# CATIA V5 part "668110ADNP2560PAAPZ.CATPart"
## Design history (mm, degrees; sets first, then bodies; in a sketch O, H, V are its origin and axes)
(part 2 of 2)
    point P17 (-10.9793, 9.5)
    point P18 (-10.4378, 10.4378)
    line L9 (-10.9793, 9.5) -> (-10.4378, 10.4378)
    point P19 (-10.4378, 10.4378)
    point P20 (-9.5, 10.9793)
    line L10 (-10.4378, 10.4378) -> (-9.5, 10.9793)
    point P21 (-9.5, 10.9793)
    point P22 (-9.5, 12.0622)
    line L11 (-9.5, 10.9793) -> (-9.5, 12.0622)
    point P23 (-9.5, 12.0622)
    point P24 (-8.9585, 13)
    line L12 (-9.5, 12.0622) -> (-8.9585, 13)
    point P25 (-8.9585, 13)
    point P26 (-9.5, 13.9378)
    line L13 (-8.9585, 13) -> (-9.5, 13.9378)
    point P27 (-9.5, 13.9378)
    point P28 (-9.5, 15.0207)
    line L14 (-9.5, 13.9378) -> (-9.5, 15.0207)
    point P29 (-9.5, 15.0207)
    point P30 (-10.4378, 15.5622)
    line L15 (-9.5, 15.0207) -> (-10.4378, 15.5622)
    point P31 (-10.4378, 15.5622)
    point P32 (-10.9793, 16.5)
    line L16 (-10.4378, 15.5622) -> (-10.9793, 16.5)
    point P33 (-10.9793, 16.5)
    point P34 (-12.0622, 16.5)
    line L17 (-10.9793, 16.5) -> (-12.0622, 16.5)
    point P35 (-12.0622, 16.5)
    point P36 (-13, 17.0415)
    line L18 (-12.0622, 16.5) -> (-13, 17.0415)
    point P37 (-13, 17.0415)
    point P38 (-13.9378, 16.5)
    line L19 (-13, 17.0415) -> (-13.9378, 16.5)
    point P39 (-13.9378, 16.5)
    point P40 (-15.0207, 16.5)
    line L20 (-13.9378, 16.5) -> (-15.0207, 16.5)
    point P41 (-15.0207, 16.5)
    point P42 (-15.5622, 15.5622)
    line L21 (-15.0207, 16.5) -> (-15.5622, 15.5622)
    point P43 (-15.5622, 15.5622)
    point P44 (-16.5, 15.0207)
    line L22 (-15.5622, 15.5622) -> (-16.5, 15.0207)
    point P45 (-16.5, 15.0207)
    point P46 (-16.5, 13.9378)
    line L23 (-16.5, 15.0207) -> (-16.5, 13.9378)
    point P47 (-16.5, 13.9378)
    point P48 (-17.0415, 13)
    line L24 (-16.5, 13.9378) -> (-17.0415, 13)
    coincidence: P1 P48, P2 P3, P4 P5, P6 P7, P8 P9, P10 P11, P12 P13, P14 P15, P16 P17, P18 P19, P20 P21, P22 P23, P24 P25, P26 P27, P28 P29, P30 P31, P32 P33, P34 P35, P36 P37, P38 P39, P40 P41, P42 P43, P44 P45, P46 P47
  Pocket3: profile Sketch24, direction (0, 0, -1), length 4.4
  Sketch25 on Plane25, origin (0, 0, 0), H (1, 0, 0), V (0, 1, 0)
    point P1 (8.9585, -13)
    point P2 (9.5, -13.9378)
    line L1 (8.9585, -13) -> (9.5, -13.9378)
    point P3 (9.5, -13.9378)
    point P4 (9.5, -15.0207)
    line L2 (9.5, -13.9378) -> (9.5, -15.0207)
    point P5 (9.5, -15.0207)
    point P6 (10.4378, -15.5622)
    line L3 (9.5, -15.0207) -> (10.4378, -15.5622)
    point P7 (10.4378, -15.5622)
    point P8 (10.9793, -16.5)
    line L4 (10.4378, -15.5622) -> (10.9793, -16.5)
    point P9 (10.9793, -16.5)
    point P10 (12.0622, -16.5)
    line L5 (10.9793, -16.5) -> (12.0622, -16.5)
    point P11 (12.0622, -16.5)
    point P12 (13, -17.0415)
    line L6 (12.0622, -16.5) -> (13, -17.0415)
    point P13 (13, -17.0415)
    point P14 (13.9378, -16.5)
    line L7 (13, -17.0415) -> (13.9378, -16.5)
    point P15 (13.9378, -16.5)
    point P16 (15.0207, -16.5)
    line L8 (13.9378, -16.5) -> (15.0207, -16.5)
    point P17 (15.0207, -16.5)
    point P18 (15.5622, -15.5622)
    line L9 (15.0207, -16.5) -> (15.5622, -15.5622)
    point P19 (15.5622, -15.5622)
    point P20 (16.5, -15.0207)
    line L10 (15.5622, -15.5622) -> (16.5, -15.0207)
    point P21 (16.5, -15.0207)
    point P22 (16.5, -13.9378)
    line L11 (16.5, -15.0207) -> (16.5, -13.9378)
    point P23 (16.5, -13.9378)
    point P24 (17.0415, -13)
    line L12 (16.5, -13.9378) -> (17.0415, -13)
    point P25 (17.0415, -13)
    point P26 (16.5, -12.0622)
    line L13 (17.0415, -13) -> (16.5, -12.0622)
    point P27 (16.5, -12.0622)
    point P28 (16.5, -10.9793)
    line L14 (16.5, -12.0622) -> (16.5, -10.9793)
    point P29 (16.5, -10.9793)
    point P30 (15.5622, -10.4378)
    line L15 (16.5, -10.9793) -> (15.5622, -10.4378)
    point P31 (15.5622, -10.4378)
    point P32 (15.0207, -9.5)
    line L16 (15.5622, -10.4378) -> (15.0207, -9.5)
    point P33 (15.0207, -9.5)
    point P34 (13.9378, -9.5)
    line L17 (15.0207, -9.5) -> (13.9378, -9.5)
    point P35 (13.9378, -9.5)
    point P36 (13, -8.9585)
    line L18 (13.9378, -9.5) -> (13, -8.9585)
    point P37 (13, -8.9585)
    point P38 (12.0622, -9.5)
    line L19 (13, -8.9585) -> (12.0622, -9.5)
    point P39 (12.0622, -9.5)
    point P40 (10.9793, -9.5)
    line L20 (12.0622, -9.5) -> (10.9793, -9.5)
    point P41 (10.9793, -9.5)
    point P42 (10.4378, -10.4378)
    line L21 (10.9793, -9.5) -> (10.4378, -10.4378)
    point P43 (10.4378, -10.4378)
    point P44 (9.5, -10.9793)
    line L22 (10.4378, -10.4378) -> (9.5, -10.9793)
    point P45 (9.5, -10.9793)
    point P46 (9.5, -12.0622)
    line L23 (9.5, -10.9793) -> (9.5, -12.0622)
    point P47 (9.5, -12.0622)
    point P48 (8.9585, -13)
    line L24 (9.5, -12.0622) -> (8.9585, -13)
    coincidence: P1 P48, P2 P3, P4 P5, P6 P7, P8 P9, P10 P11, P12 P13, P14 P15, P16 P17, P18 P19, P20 P21, P22 P23, P24 P25, P26 P27, P28 P29, P30 P31, P32 P33, P34 P35, P36 P37, P38 P39, P40 P41, P42 P43, P44 P45, P46 P47
  Pocket4: profile Sketch25, direction (0, 0, -1), length 4.4
  Sketch26 on Plane26, origin (0, 0, 0), H (1, 0, 0), V (0, 1, 0)
    point P1 (8.9585, 13)
    point P2 (9.5, 12.0622)
    line L1 (8.9585, 13) -> (9.5, 12.0622)
    point P3 (9.5, 12.0622)
    point P4 (9.5, 10.9793)
    line L2 (9.5, 12.0622) -> (9.5, 10.9793)
    point P5 (9.5, 10.9793)
    point P6 (10.4378, 10.4378)
    line L3 (9.5, 10.9793) -> (10.4378, 10.4378)
    point P7 (10.4378, 10.4378)
    point P8 (10.9793, 9.5)
    line L4 (10.4378, 10.4378) -> (10.9793, 9.5)
    point P9 (10.9793, 9.5)
    point P10 (12.0622, 9.5)
    line L5 (10.9793, 9.5) -> (12.0622, 9.5)
    point P11 (12.0622, 9.5)
    point P12 (13, 8.9585)
    line L6 (12.0622, 9.5) -> (13, 8.9585)
    point P13 (13, 8.9585)
    point P14 (13.9378, 9.5)
    line L7 (13, 8.9585) -> (13.9378, 9.5)
    point P15 (13.9378, 9.5)
    point P16 (15.0207, 9.5)
    line L8 (13.9378, 9.5) -> (15.0207, 9.5)
    point P17 (15.0207, 9.5)
    point P18 (15.5622, 10.4378)
    line L9 (15.0207, 9.5) -> (15.5622, 10.4378)
    point P19 (15.5622, 10.4378)
    point P20 (16.5, 10.9793)
    line L10 (15.5622, 10.4378) -> (16.5, 10.9793)
    point P21 (16.5, 10.9793)
    point P22 (16.5, 12.0622)
    line L11 (16.5, 10.9793) -> (16.5, 12.0622)
    point P23 (16.5, 12.0622)
    point P24 (17.0415, 13)
    line L12 (16.5, 12.0622) -> (17.0415, 13)
    point P25 (17.0415, 13)
    point P26 (16.5, 13.9378)
    line L13 (17.0415, 13) -> (16.5, 13.9378)
    point P27 (16.5, 13.9378)
    point P28 (16.5, 15.0207)
    line L14 (16.5, 13.9378) -> (16.5, 15.0207)
    point P29 (16.5, 15.0207)
    point P30 (15.5622, 15.5622)
    line L15 (16.5, 15.0207) -> (15.5622, 15.5622)
    point P31 (15.5622, 15.5622)
    point P32 (15.0207, 16.5)
    line L16 (15.5622, 15.5622) -> (15.0207, 16.5)
    point P33 (15.0207, 16.5)
    point P34 (13.9378, 16.5)
    line L17 (15.0207, 16.5) -> (13.9378, 16.5)
    point P35 (13.9378, 16.5)
    point P36 (13, 17.0415)
    line L18 (13.9378, 16.5) -> (13, 17.0415)
    point P37 (13, 17.0415)
    point P38 (12.0622, 16.5)
    line L19 (13, 17.0415) -> (12.0622, 16.5)
    point P39 (12.0622, 16.5)
    point P40 (10.9793, 16.5)
    line L20 (12.0622, 16.5) -> (10.9793, 16.5)
    point P41 (10.9793, 16.5)
    point P42 (10.4378, 15.5622)
    line L21 (10.9793, 16.5) -> (10.4378, 15.5622)
    point P43 (10.4378, 15.5622)
    point P44 (9.5, 15.0207)
    line L22 (10.4378, 15.5622) -> (9.5, 15.0207)
    point P45 (9.5, 15.0207)
    point P46 (9.5, 13.9378)
    line L23 (9.5, 15.0207) -> (9.5, 13.9378)
    point P47 (9.5, 13.9378)
    point P48 (8.9585, 13)
    line L24 (9.5, 13.9378) -> (8.9585, 13)
    coincidence: P1 P48, P2 P3, P4 P5, P6 P7, P8 P9, P10 P11, P12 P13, P14 P15, P16 P17, P18 P19, P20 P21, P22 P23, P24 P25, P26 P27, P28 P29, P30 P31, P32 P33, P34 P35, P36 P37, P38 P39, P40 P41, P42 P43, P44 P45, P46 P47
  Pocket5: profile Sketch26, direction (0, 0, -1), length 4.4
  Sketch27 on Plane27, origin (0, 0, -99), H (1, 0, 0), V (0, 1, 0)
    point P1 (-17.0415, 13)
    point P2 (-16.5, 12.0622)
    line L1 (-17.0415, 13) -> (-16.5, 12.0622)
    point P3 (-16.5, 12.0622)
    point P4 (-16.5, 10.9793)
    line L2 (-16.5, 12.0622) -> (-16.5, 10.9793)
    point P5 (-16.5, 10.9793)
    point P6 (-15.5622, 10.4378)
    line L3 (-16.5, 10.9793) -> (-15.5622, 10.4378)
    point P7 (-15.5622, 10.4378)
    point P8 (-15.0207, 9.5)
    line L4 (-15.5622, 10.4378) -> (-15.0207, 9.5)
    point P9 (-15.0207, 9.5)
    point P10 (-13.9378, 9.5)
    line L5 (-15.0207, 9.5) -> (-13.9378, 9.5)
    point P11 (-13.9378, 9.5)
    point P12 (-13, 8.9585)
    line L6 (-13.9378, 9.5) -> (-13, 8.9585)
    point P13 (-13, 8.9585)
    point P14 (-12.0622, 9.5)
    line L7 (-13, 8.9585) -> (-12.0622, 9.5)
    point P15 (-12.0622, 9.5)
    point P16 (-10.9793, 9.5)
    line L8 (-12.0622, 9.5) -> (-10.9793, 9.5)
    point P17 (-10.9793, 9.5)
    point P18 (-10.4378, 10.4378)
    line L9 (-10.9793, 9.5) -> (-10.4378, 10.4378)
    point P19 (-10.4378, 10.4378)
    point P20 (-9.5, 10.9793)
    line L10 (-10.4378, 10.4378) -> (-9.5, 10.9793)
    point P21 (-9.5, 10.9793)
    point P22 (-9.5, 12.0622)
    line L11 (-9.5, 10.9793) -> (-9.5, 12.0622)
    point P23 (-9.5, 12.0622)
    point P24 (-8.9585, 13)
    line L12 (-9.5, 12.0622) -> (-8.9585, 13)
    point P25 (-8.9585, 13)
    point P26 (-9.5, 13.9378)
    line L13 (-8.9585, 13) -> (-9.5, 13.9378)
    point P27 (-9.5, 13.9378)
    point P28 (-9.5, 15.0207)
    line L14 (-9.5, 13.9378) -> (-9.5, 15.0207)
    point P29 (-9.5, 15.0207)
    point P30 (-10.4378, 15.5622)
    line L15 (-9.5, 15.0207) -> (-10.4378, 15.5622)
    point P31 (-10.4378, 15.5622)
    point P32 (-10.9793, 16.5)
    line L16 (-10.4378, 15.5622) -> (-10.9793, 16.5)
    point P33 (-10.9793, 16.5)
    point P34 (-12.0622, 16.5)
    line L17 (-10.9793, 16.5) -> (-12.0622, 16.5)
    point P35 (-12.0622, 16.5)
    point P36 (-13, 17.0415)
    line L18 (-12.0622, 16.5) -> (-13, 17.0415)
    point P37 (-13, 17.0415)
    point P38 (-13.9378, 16.5)
    line L19 (-13, 17.0415) -> (-13.9378, 16.5)
    point P39 (-13.9378, 16.5)
    point P40 (-15.0207, 16.5)
    line L20 (-13.9378, 16.5) -> (-15.0207, 16.5)
    point P41 (-15.0207, 16.5)
    point P42 (-15.5622, 15.5622)
    line L21 (-15.0207, 16.5) -> (-15.5622, 15.5622)
    point P43 (-15.5622, 15.5622)
    point P44 (-16.5, 15.0207)
    line L22 (-15.5622, 15.5622) -> (-16.5, 15.0207)
    point P45 (-16.5, 15.0207)
    point P46 (-16.5, 13.9378)
    line L23 (-16.5, 15.0207) -> (-16.5, 13.9378)
    point P47 (-16.5, 13.9378)
    point P48 (-17.0415, 13)
    line L24 (-16.5, 13.9378) -> (-17.0415, 13)
    coincidence: P1 P48, P2 P3, P4 P5, P6 P7, P8 P9, P10 P11, P12 P13, P14 P15, P16 P17, P18 P19, P20 P21, P22 P23, P24 P25, P26 P27, P28 P29, P30 P31, P32 P33, P34 P35, P36 P37, P38 P39, P40 P41, P42 P43, P44 P45, P46 P47
  Pocket6: profile Sketch27, direction (0, 0, 1), length 4.4
  Sketch28 on Plane28, origin (0, 0, -99), H (1, 0, 0), V (0, 1, 0)
    point P1 (-17.0415, -13)
    point P2 (-16.5, -13.9378)
    line L1 (-17.0415, -13) -> (-16.5, -13.9378)
    point P3 (-16.5, -13.9378)
    point P4 (-16.5, -15.0207)
    line L2 (-16.5, -13.9378) -> (-16.5, -15.0207)
    point P5 (-16.5, -15.0207)
    point P6 (-15.5622, -15.5622)
    line L3 (-16.5, -15.0207) -> (-15.5622, -15.5622)
    point P7 (-15.5622, -15.5622)
    point P8 (-15.0207, -16.5)
    line L4 (-15.5622, -15.5622) -> (-15.0207, -16.5)
    point P9 (-15.0207, -16.5)
    point P10 (-13.9378, -16.5)
    line L5 (-15.0207, -16.5) -> (-13.9378, -16.5)
    point P11 (-13.9378, -16.5)
    point P12 (-13, -17.0415)
    line L6 (-13.9378, -16.5) -> (-13, -17.0415)
    point P13 (-13, -17.0415)
    point P14 (-12.0622, -16.5)
    line L7 (-13, -17.0415) -> (-12.0622, -16.5)
    point P15 (-12.0622, -16.5)
    point P16 (-10.9793, -16.5)
    line L8 (-12.0622, -16.5) -> (-10.9793, -16.5)
    point P17 (-10.9793, -16.5)
    point P18 (-10.4378, -15.5622)
    line L9 (-10.9793, -16.5) -> (-10.4378, -15.5622)
    point P19 (-10.4378, -15.5622)
    point P20 (-9.5, -15.0207)
    line L10 (-10.4378, -15.5622) -> (-9.5, -15.0207)
    point P21 (-9.5, -15.0207)
    point P22 (-9.5, -13.9378)
    line L11 (-9.5, -15.0207) -> (-9.5, -13.9378)
    point P23 (-9.5, -13.9378)
    point P24 (-8.9585, -13)
    line L12 (-9.5, -13.9378) -> (-8.9585, -13)
    point P25 (-8.9585, -13)
    point P26 (-9.5, -12.0622)
    line L13 (-8.9585, -13) -> (-9.5, -12.0622)
    point P27 (-9.5, -12.0622)
    point P28 (-9.5, -10.9793)
    line L14 (-9.5, -12.0622) -> (-9.5, -10.9793)
    point P29 (-9.5, -10.9793)
    point P30 (-10.4378, -10.4378)
    line L15 (-9.5, -10.9793) -> (-10.4378, -10.4378)
    point P31 (-10.4378, -10.4378)
    point P32 (-10.9793, -9.5)
    line L16 (-10.4378, -10.4378) -> (-10.9793, -9.5)
    point P33 (-10.9793, -9.5)
    point P34 (-12.0622, -9.5)
    line L17 (-10.9793, -9.5) -> (-12.0622, -9.5)
    point P35 (-12.0622, -9.5)
    point P36 (-13, -8.9585)
    line L18 (-12.0622, -9.5) -> (-13, -8.9585)
    point P37 (-13, -8.9585)
    point P38 (-13.9378, -9.5)
    line L19 (-13, -8.9585) -> (-13.9378, -9.5)
    point P39 (-13.9378, -9.5)
    point P40 (-15.0207, -9.5)
    line L20 (-13.9378, -9.5) -> (-15.0207, -9.5)
    point P41 (-15.0207, -9.5)
    point P42 (-15.5622, -10.4378)
    line L21 (-15.0207, -9.5) -> (-15.5622, -10.4378)
    point P43 (-15.5622, -10.4378)
    point P44 (-16.5, -10.9793)
    line L22 (-15.5622, -10.4378) -> (-16.5, -10.9793)
    point P45 (-16.5, -10.9793)
    point P46 (-16.5, -12.0622)
    line L23 (-16.5, -10.9793) -> (-16.5, -12.0622)
    point P47 (-16.5, -12.0622)
    point P48 (-17.0415, -13)
    line L24 (-16.5, -12.0622) -> (-17.0415, -13)
    coincidence: P1 P48, P2 P3, P4 P5, P6 P7, P8 P9, P10 P11, P12 P13, P14 P15, P16 P17, P18 P19, P20 P21, P22 P23, P24 P25, P26 P27, P28 P29, P30 P31, P32 P33, P34 P35, P36 P37, P38 P39, P40 P41, P42 P43, P44 P45, P46 P47
  Pocket7: profile Sketch28, direction (0, 0, 1), length 4.4
  Sketch29 on Plane29, origin (0, 0, -99), H (1, 0, 0), V (0, 1, 0)
    point P1 (8.9585, -13)
    point P2 (9.5, -13.9378)
    line L1 (8.9585, -13) -> (9.5, -13.9378)
    point P3 (9.5, -13.9378)
    point P4 (9.5, -15.0207)
    line L2 (9.5, -13.9378) -> (9.5, -15.0207)
    point P5 (9.5, -15.0207)
    point P6 (10.4378, -15.5622)
    line L3 (9.5, -15.0207) -> (10.4378, -15.5622)
    point P7 (10.4378, -15.5622)
    point P8 (10.9793, -16.5)
    line L4 (10.4378, -15.5622) -> (10.9793, -16.5)
    point P9 (10.9793, -16.5)
    point P10 (12.0622, -16.5)
    line L5 (10.9793, -16.5) -> (12.0622, -16.5)
    point P11 (12.0622, -16.5)
    point P12 (13, -17.0415)
    line L6 (12.0622, -16.5) -> (13, -17.0415)
    point P13 (13, -17.0415)
    point P14 (13.9378, -16.5)
    line L7 (13, -17.0415) -> (13.9378, -16.5)
    point P15 (13.9378, -16.5)
    point P16 (15.0207, -16.5)
    line L8 (13.9378, -16.5) -> (15.0207, -16.5)
    point P17 (15.0207, -16.5)
    point P18 (15.5622, -15.5622)
    line L9 (15.0207, -16.5) -> (15.5622, -15.5622)
    point P19 (15.5622, -15.5622)
    point P20 (16.5, -15.0207)
    line L10 (15.5622, -15.5622) -> (16.5, -15.0207)
    point P21 (16.5, -15.0207)
    point P22 (16.5, -13.9378)
    line L11 (16.5, -15.0207) -> (16.5, -13.9378)
    point P23 (16.5, -13.9378)
    point P24 (17.0415, -13)
    line L12 (16.5, -13.9378) -> (17.0415, -13)
    point P25 (17.0415, -13)
    point P26 (16.5, -12.0622)
    line L13 (17.0415, -13) -> (16.5, -12.0622)
    point P27 (16.5, -12.0622)
    point P28 (16.5, -10.9793)
    line L14 (16.5, -12.0622) -> (16.5, -10.9793)
    point P29 (16.5, -10.9793)
    point P30 (15.5622, -10.4378)
    line L15 (16.5, -10.9793) -> (15.5622, -10.4378)
    point P31 (15.5622, -10.4378)
    point P32 (15.0207, -9.5)
    line L16 (15.5622, -10.4378) -> (15.0207, -9.5)
    point P33 (15.0207, -9.5)
    point P34 (13.9378, -9.5)
    line L17 (15.0207, -9.5) -> (13.9378, -9.5)
    point P35 (13.9378, -9.5)
    point P36 (13, -8.9585)
    line L18 (13.9378, -9.5) -> (13, -8.9585)
    point P37 (13, -8.9585)
    point P38 (12.0622, -9.5)
    line L19 (13, -8.9585) -> (12.0622, -9.5)
    point P39 (12.0622, -9.5)
    point P40 (10.9793, -9.5)
    line L20 (12.0622, -9.5) -> (10.9793, -9.5)
    point P41 (10.9793, -9.5)
    point P42 (10.4378, -10.4378)
    line L21 (10.9793, -9.5) -> (10.4378, -10.4378)
    point P43 (10.4378, -10.4378)
    point P44 (9.5, -10.9793)
    line L22 (10.4378, -10.4378) -> (9.5, -10.9793)
    point P45 (9.5, -10.9793)
    point P46 (9.5, -12.0622)
    line L23 (9.5, -10.9793) -> (9.5, -12.0622)
    point P47 (9.5, -12.0622)
    point P48 (8.9585, -13)
    line L24 (9.5, -12.0622) -> (8.9585, -13)
    coincidence: P1 P48, P2 P3, P4 P5, P6 P7, P8 P9, P10 P11, P12 P13, P14 P15, P16 P17, P18 P19, P20 P21, P22 P23, P24 P25, P26 P27, P28 P29, P30 P31, P32 P33, P34 P35, P36 P37, P38 P39, P40 P41, P42 P43, P44 P45, P46 P47
  Pocket8: profile Sketch29, direction (0, 0, 1), length 4.4
  Sketch30 on Plane30, origin (0, 0, -99), H (1, 0, 0), V (0, 1, 0)
    point P1 (8.9585, 13)
    point P2 (9.5, 12.0622)
    line L1 (8.9585, 13) -> (9.5, 12.0622)
    point P3 (9.5, 12.0622)
    point P4 (9.5, 10.9793)
    line L2 (9.5, 12.0622) -> (9.5, 10.9793)
    point P5 (9.5, 10.9793)
    point P6 (10.4378, 10.4378)
    line L3 (9.5, 10.9793) -> (10.4378, 10.4378)
    point P7 (10.4378, 10.4378)
    point P8 (10.9793, 9.5)
    line L4 (10.4378, 10.4378) -> (10.9793, 9.5)
    point P9 (10.9793, 9.5)
    point P10 (12.0622, 9.5)
    line L5 (10.9793, 9.5) -> (12.0622, 9.5)
    point P11 (12.0622, 9.5)
    point P12 (13, 8.9585)
    line L6 (12.0622, 9.5) -> (13, 8.9585)
    point P13 (13, 8.9585)
    point P14 (13.9378, 9.5)
    line L7 (13, 8.9585) -> (13.9378, 9.5)
    point P15 (13.9378, 9.5)
    point P16 (15.0207, 9.5)
    line L8 (13.9378, 9.5) -> (15.0207, 9.5)
    point P17 (15.0207, 9.5)
    point P18 (15.5622, 10.4378)
    line L9 (15.0207, 9.5) -> (15.5622, 10.4378)
    point P19 (15.5622, 10.4378)
    point P20 (16.5, 10.9793)
    line L10 (15.5622, 10.4378) -> (16.5, 10.9793)
    point P21 (16.5, 10.9793)
    point P22 (16.5, 12.0622)
    line L11 (16.5, 10.9793) -> (16.5, 12.0622)
    point P23 (16.5, 12.0622)
    point P24 (17.0415, 13)
    line L12 (16.5, 12.0622) -> (17.0415, 13)
    point P25 (17.0415, 13)
    point P26 (16.5, 13.9378)
    line L13 (17.0415, 13) -> (16.5, 13.9378)
    point P27 (16.5, 13.9378)
    point P28 (16.5, 15.0207)
    line L14 (16.5, 13.9378) -> (16.5, 15.0207)
    point P29 (16.5, 15.0207)
    point P30 (15.5622, 15.5622)
    line L15 (16.5, 15.0207) -> (15.5622, 15.5622)
    point P31 (15.5622, 15.5622)
    point P32 (15.0207, 16.5)
    line L16 (15.5622, 15.5622) -> (15.0207, 16.5)
    point P33 (15.0207, 16.5)
    point P34 (13.9378, 16.5)
    line L17 (15.0207, 16.5) -> (13.9378, 16.5)
    point P35 (13.9378, 16.5)
    point P36 (13, 17.0415)
    line L18 (13.9378, 16.5) -> (13, 17.0415)
    point P37 (13, 17.0415)
    point P38 (12.0622, 16.5)
    line L19 (13, 17.0415) -> (12.0622, 16.5)
    point P39 (12.0622, 16.5)
    point P40 (10.9793, 16.5)
    line L20 (12.0622, 16.5) -> (10.9793, 16.5)
    point P41 (10.9793, 16.5)
    point P42 (10.4378, 15.5622)
    line L21 (10.9793, 16.5) -> (10.4378, 15.5622)
    point P43 (10.4378, 15.5622)
    point P44 (9.5, 15.0207)
    line L22 (10.4378, 15.5622) -> (9.5, 15.0207)
    point P45 (9.5, 15.0207)
    point P46 (9.5, 13.9378)
    line L23 (9.5, 15.0207) -> (9.5, 13.9378)
    point P47 (9.5, 13.9378)
    point P48 (8.9585, 13)
    line L24 (9.5, 13.9378) -> (8.9585, 13)
    coincidence: P1 P48, P2 P3, P4 P5, P6 P7, P8 P9, P10 P11, P12 P13, P14 P15, P16 P17, P18 P19, P20 P21, P22 P23, P24 P25, P26 P27, P28 P29, P30 P31, P32 P33, P34 P35, P36 P37, P38 P39, P40 P41, P42 P43, P44 P45, P46 P47
  Pocket9: profile Sketch30, direction (0, 0, 1), length 4.4
  Sketch31 on Plane31, origin (13, 0, 0), H (0, 0, -1), V (0, 1, 0)
    point P1 (19.5, -13)
    point P2 (19.5, -10.95)
    line L1 (19.5, -13) -> (19.5, -10.95)
    point P3 (19.5, -10.95)
    point P4 (79.5, -10.95)
    line L2 (19.5, -10.95) -> (79.5, -10.95)
    point P5 (79.5, -10.95)
    point P6 (79.5, -13)
    line L3 (79.5, -10.95) -> (79.5, -13)
    point P7 (79.5, -13)
    point P8 (19.5, -13)
    line L4 (79.5, -13) -> (19.5, -13)
    point P9 (79.5, -13)
    point P10 (19.5, -13)
    axis line L5 (79.5, -13) -> (19.5, -13)
    coincidence: P1 P8, P2 P3, P4 P5, P6 P7
  Groove13: profile Sketch31, axis Sketch31.L5, angle 0, second angle 360
  Sketch32 on Plane32, origin (13, 0, 0), H (0, 0, -1), V (0, 1, 0)
    point P1 (19.5, 13)
    point P2 (19.5, 15.05)
    line L1 (19.5, 13) -> (19.5, 15.05)
    point P3 (19.5, 15.05)
    point P4 (79.5, 15.05)
    line L2 (19.5, 15.05) -> (79.5, 15.05)
    point P5 (79.5, 15.05)
    point P6 (79.5, 13)
    line L3 (79.5, 15.05) -> (79.5, 13)
    point P7 (79.5, 13)
    point P8 (19.5, 13)
    line L4 (79.5, 13) -> (19.5, 13)
    point P9 (79.5, 13)
    point P10 (19.5, 13)
    axis line L5 (79.5, 13) -> (19.5, 13)
    coincidence: P1 P8, P2 P3, P4 P5, P6 P7
  Groove14: profile Sketch32, axis Sketch32.L5, angle 0, second angle 360
  Sketch33 on Plane33, origin (-13, 0, 0), H (0, 0, -1), V (0, 1, 0)
    point P1 (19.5, -13)
    point P2 (19.5, -10.95)
    line L1 (19.5, -13) -> (19.5, -10.95)
    point P3 (19.5, -10.95)
    point P4 (79.5, -10.95)
    line L2 (19.5, -10.95) -> (79.5, -10.95)
    point P5 (79.5, -10.95)
    point P6 (79.5, -13)
    line L3 (79.5, -10.95) -> (79.5, -13)
    point P7 (79.5, -13)
    point P8 (19.5, -13)
    line L4 (79.5, -13) -> (19.5, -13)
    point P9 (79.5, -13)
    point P10 (19.5, -13)
    axis line L5 (79.5, -13) -> (19.5, -13)
    coincidence: P1 P8, P2 P3, P4 P5, P6 P7
  Groove15: profile Sketch33, axis Sketch33.L5, angle 0, second angle 360
  Sketch34 on Plane34, origin (-13, 0, 0), H (0, 0, -1), V (0, 1, 0)
    point P1 (19.5, 13)
    point P2 (19.5, 15.05)
    line L1 (19.5, 13) -> (19.5, 15.05)
    point P3 (19.5, 15.05)
    point P4 (79.5, 15.05)
    line L2 (19.5, 15.05) -> (79.5, 15.05)
    point P5 (79.5, 15.05)
    point P6 (79.5, 13)
    line L3 (79.5, 15.05) -> (79.5, 13)
    point P7 (79.5, 13)
    point P8 (19.5, 13)
    line L4 (79.5, 13) -> (19.5, 13)
    point P9 (79.5, 13)
    point P10 (19.5, 13)
    axis line L5 (79.5, 13) -> (19.5, 13)
    coincidence: P1 P8, P2 P3, P4 P5, P6 P7
  Groove16: profile Sketch34, axis Sketch34.L5, angle 0, second angle 360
